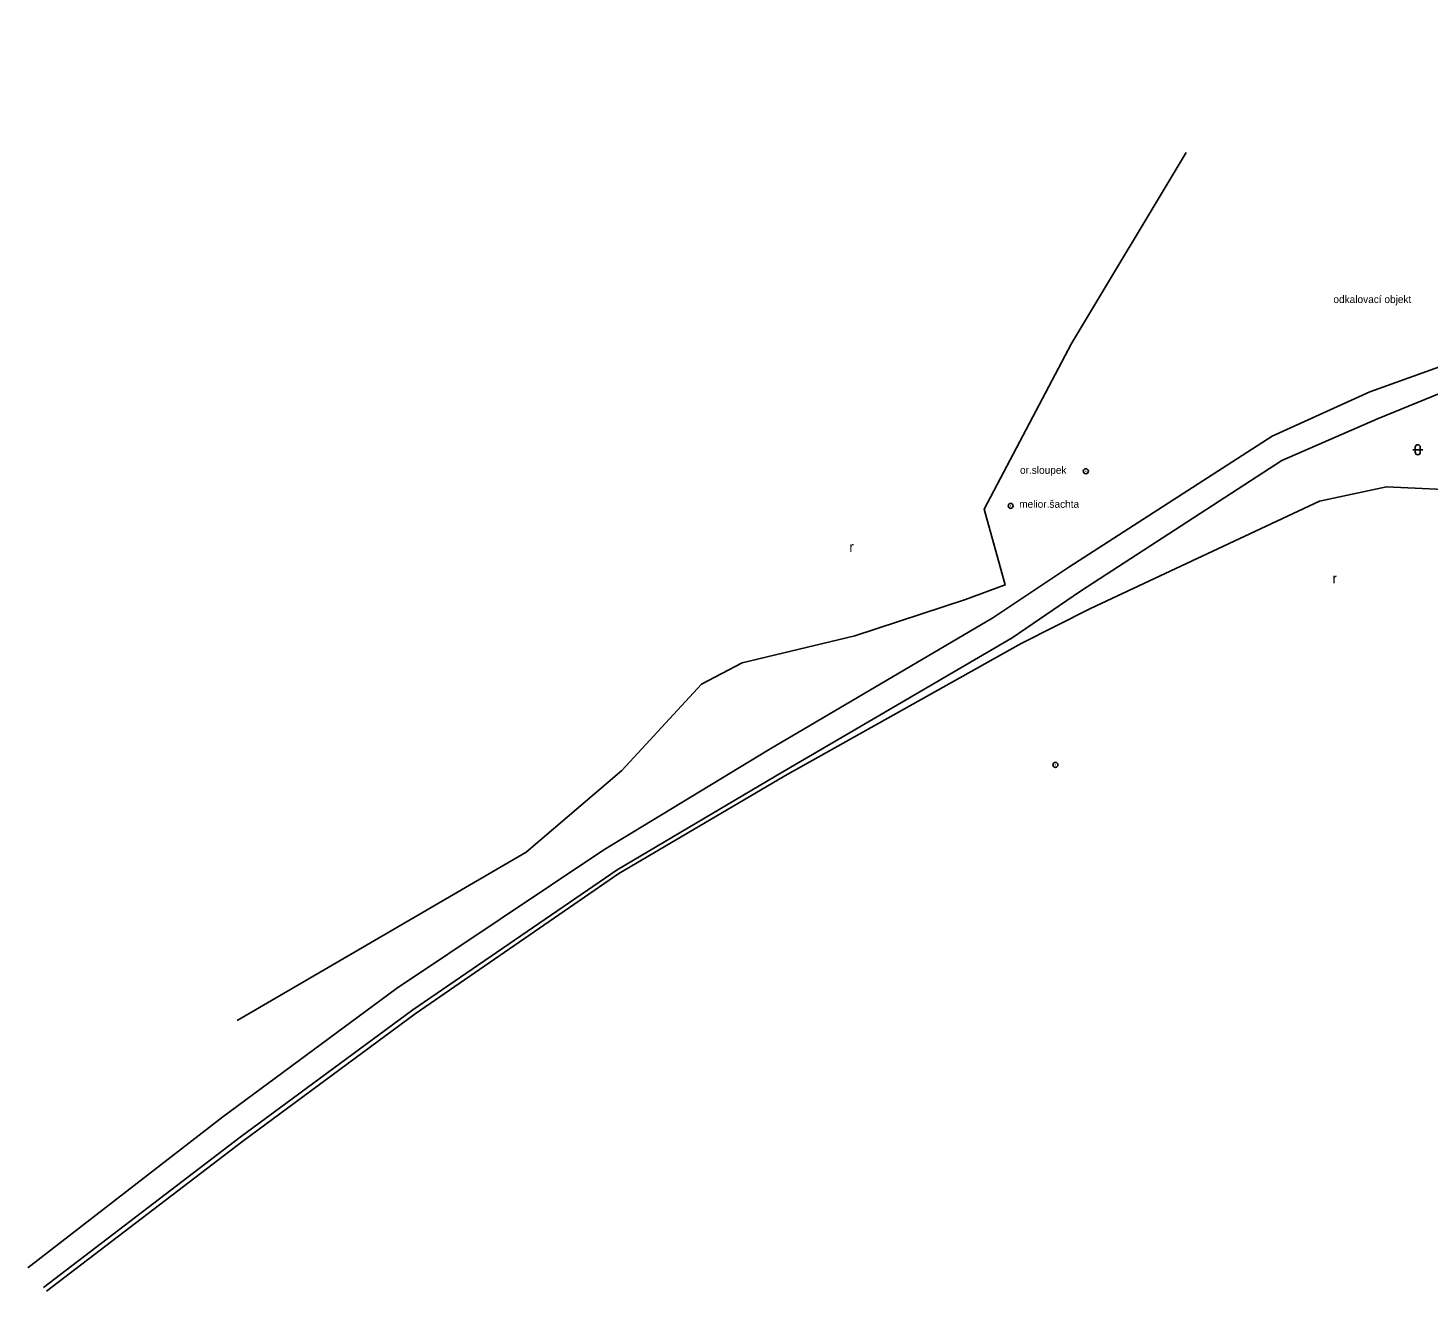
# Model space of a CAD drawing. Extents: x -762483 to -761175, y -1154655 to -1152452.
# Drawn here: x -761515.2 to -761375.9, y -1154466.5 to -1154340.8 of the extents above; entities that cross this region are included whole.
import ezdxf

# ---------------------------------------------------------------- set-up
doc = ezdxf.new("R2010")
doc.units = 0
for name, color, linetype in [('POMOC_POPIS', 7, 'Continuous'), ('ROZHRANÍ_PLOCH', 7, 'Continuous'), ('ZELEŇ', 7, 'Continuous'), ('ZN_DOPLŇKOVÉ', 7, 'Continuous'), ('ZN_KULTUR', 7, 'Continuous')]:
    doc.layers.add(name, color=color, linetype=linetype)

msp = doc.modelspace()

# ---------------------------------------------------------------- linework, layer by layer
at = {"layer": 'ROZHRANÍ_PLOCH'}
for points in [[(-761309.55, -1154340.82), (-761308.45, -1154345.56), (-761317.63, -1154351.07), (-761334.66, -1154360.15), (-761356.11, -1154369.32), (-761361.72, -1154371), (-761370.86, -1154373.15), (-761381.66, -1154377.03), (-761391.38, -1154381.44), (-761411.61, -1154394.48), (-761419.15, -1154399.51), (-761441.43, -1154412.61), (-761457.86, -1154422.59), (-761478.49, -1154436.4), (-761495.76, -1154449.16), (-761515.15, -1154464.19)], [(-761513.61, -1154466.13), (-761494.05, -1154451.17), (-761476.85, -1154438.5), (-761456.54, -1154424.58), (-761440.07, -1154414.83), (-761417.23, -1154401.5), (-761410.45, -1154396.86), (-761390.4, -1154383.87), (-761380.89, -1154379.71), (-761370.01, -1154375.25), (-761360.85, -1154373.41)]]:
    msp.add_lwpolyline(points, dxfattribs=at)
at = {"layer": 'ZELEŇ'}
for points in [[(-761494.33, -1154439.56), (-761465.59, -1154422.81), (-761456.06, -1154414.71), (-761448.16, -1154406.12), (-761444.1, -1154403.98), (-761432.9, -1154401.3), (-761421.87, -1154397.68), (-761417.92, -1154396.24), (-761420.02, -1154388.71), (-761411.34, -1154372.2), (-761399.92, -1154353.21)], [(-761367.1, -1154392.76), (-761371.47, -1154386.87), (-761380, -1154386.46), (-761386.65, -1154387.9), (-761409.46, -1154398.58), (-761416.35, -1154402.05), (-761439.84, -1154415.22), (-761456.36, -1154424.96), (-761476.64, -1154438.92), (-761493.77, -1154451.58), (-761513.32, -1154466.49)]]:
    msp.add_lwpolyline(points, dxfattribs=at)
at = {"layer": 'ZN_DOPLŇKOVÉ'}
for centre, radius in [((-761409.91, -1154384.93), 0.25), ((-761409.91, -1154384.93), 0.0005), ((-761417.39, -1154388.37), 0.25), ((-761417.39, -1154388.37), 0.0005), ((-761412.94, -1154414.14), 0.25), ((-761412.94, -1154414.14), 0.0005)]:
    msp.add_circle(centre, radius, dxfattribs=at)
at = {"layer": 'ZN_KULTUR'}
for p, q in [((-761377.39, -1154382.79), (-761376.39, -1154382.79)), ((-761377.14, -1154383.04), (-761377.14, -1154382.54)), ((-761376.64, -1154383.04), (-761376.64, -1154382.54))]:
    msp.add_line(p, q, dxfattribs=at)
for centre, start, end in [((-761376.89, -1154382.54), 0, 180), ((-761376.89, -1154383.04), 180, 360)]:
    msp.add_arc(centre, 0.25, start, end, dxfattribs=at)

# ---------------------------------------------------------------- texts
at = {"layer": 'POMOC_POPIS'}
for s, p in [('odkalovací objekt', (-761385.28, -1154368.19)), ('or.sloupek', (-761416.46, -1154385.18)), ('melior.šachta', (-761416.54, -1154388.56))]:
    msp.add_text(s, height=0.75, dxfattribs=at).set_placement(p)
at = {"layer": 'ZN_KULTUR'}
for p in [(-761433.44, -1154392.95), (-761385.37, -1154396.09)]:
    msp.add_text('r', height=1, dxfattribs=at).set_placement(p)

doc.saveas('drawing.dxf')
